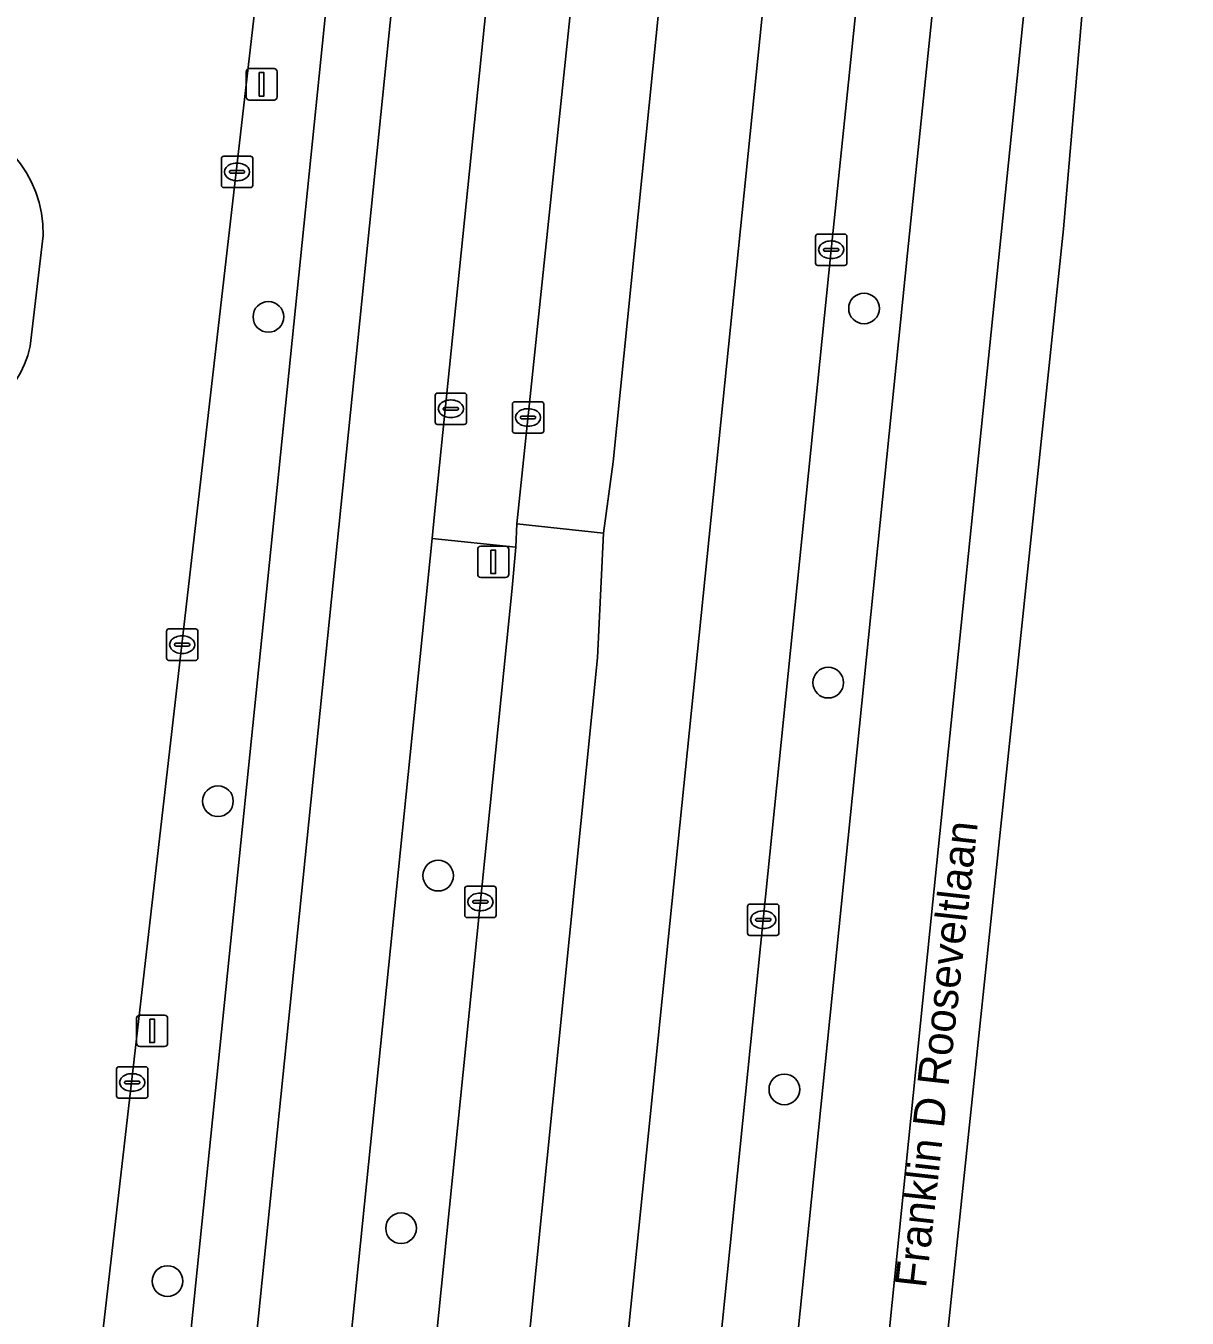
# Model space of a CAD drawing. Extents: x 160888 to 161385, y 386490 to 386908.
# Drawn here: x 161334.91 to 161371.94, y 386612.73 to 386653.93 of the extents above; entities that cross this region are included whole.
import ezdxf

# ---------------------------------------------------------------- set-up
doc = ezdxf.new("R2010")
doc.units = 0
for name, color, linetype in [('IMGEO_Berm_groen', 7, 'Continuous'), ('IMGEO_Boom', 7, 'Continuous'), ('IMGEO_Fietspad_gesloten', 7, 'Continuous'), ('IMGEO_Groenvoorziening', 7, 'Continuous'), ('IMGEO_Haag', 7, 'Continuous'), ('IMGEO_Kolk', 7, 'Continuous'), ('IMGEO_Lichtmast', 7, 'Continuous'), ('IMGEO_Openbare_ruimte_label', 7, 'Continuous'), ('IMGEO_Rijbaan_lokaal_gesloten', 7, 'Continuous'), ('IMGEO_Rijbaan_lokaal_open', 7, 'Continuous'), ('IMGEO_Voetpad_open', 7, 'Continuous')]:
    doc.layers.add(name, color=color, linetype=linetype)

msp = doc.modelspace()

# ---------------------------------------------------------------- linework, layer by layer
at = {"layer": 'IMGEO_Berm_groen'}
for points in [[(161363.024, 386646.681), (161367.022, 386685.397), (161367.598, 386691.178), (161367.683, 386693.586), (161365.398, 386693.803), (161364.593, 386685.592), (161364.125, 386681.052), (161362.491, 386665.206), (161360.59, 386646.794), (161358.423, 386625.435), (161356.553, 386606.975), (161354.948, 386591.576), (161352.778, 386570.251), (161350.673, 386549.854), (161349.854, 386541.879), (161348.259, 386526.488)], [(161350.321, 386526.461), (161352.302, 386541.627), (161357.382, 386591.194), (161359.018, 386607.209), (161363.024, 386646.681)], [(161344.884, 386581.428), (161350.408, 386635.904), (161350.537, 386637.31), (161347.861, 386637.589), (161342.161, 386581.483), (161341.141, 386571.584), (161339.032, 386551.069), (161338.136, 386542.124), (161337.443, 386534.03), (161336.548, 386526.649), (161336.452, 386525.646)]]:
    msp.add_lwpolyline(points, dxfattribs=at)
at = {"layer": 'IMGEO_Boom'}
for centre in [(161361.637, 386644.922), (161342.641, 386644.654), (161360.496, 386632.993), (161341.033, 386629.213), (161348.056, 386626.84), (161359.096, 386620.026), (161346.872, 386615.599), (161339.424, 386613.914)]:
    msp.add_circle(centre, 0.489, dxfattribs=at)
at = {"layer": 'IMGEO_Fietspad_gesloten'}
msp.add_lwpolyline([(161338.136, 386542.124), (161339.032, 386551.069), (161341.141, 386571.584), (161342.161, 386581.483), (161347.861, 386637.589), (161347.94, 386638.364), (161351.757, 386675.763), (161352.649, 386684.258), (161352.944, 386686.937), (161353.547, 386692.676), (161354.45, 386701.7), (161354.589, 386703.318), (161354.964, 386706.98), (161351.913, 386707.118), (161351.576, 386703.719), (161351.137, 386699.288), (161350.75, 386695.389), (161348.773, 386676.071), (161344.586, 386635.023), (161340.003, 386589.938), (161338.485, 386580.159)], dxfattribs=at)
at = {"layer": 'IMGEO_Groenvoorziening'}
for points in [[(161338.172, 386592.768), (161342.863, 386638.693), (161346.713, 386676.405)], [(161343.202, 386663.059), (161336.592, 386605.648), (161334.906, 386593.09), (161337.474, 386592.417)], [(161335.049, 386643.715), (161335.454, 386647.249)]]:
    msp.add_lwpolyline(points, dxfattribs=at)
for centre, radius, start, end in [((161331.73, 386647.329), 3.725, 358.7672, 84.1721), ((161331.772, 386644.452), 3.359, 267.2207, 347.325)]:
    msp.add_arc(centre, radius, start, end, dxfattribs=at)
at = {"layer": 'IMGEO_Haag'}
for points in [[(161338.172, 386592.768), (161342.863, 386638.693), (161346.713, 386676.405)], [(161343.202, 386663.059), (161336.592, 386605.648), (161334.906, 386593.09), (161337.474, 386592.417)]]:
    msp.add_lwpolyline(points, dxfattribs=at)
at = {"layer": 'IMGEO_Kolk'}
for p, q in [((161341.216, 386649.775), (161342.068, 386649.775)), ((161341.141, 386648.849), (161341.141, 386649.701)), ((161341.443, 386649.318), (161341.841, 386649.318)), ((161341.629, 386649.555), (161341.654, 386649.555)), ((161342.142, 386649.701), (161342.142, 386648.849)), ((161341.4, 386649.269), (161341.4, 386649.281)), ((161341.838, 386649.232), (161341.44, 386649.232)), ((161341.652, 386648.995), (161341.627, 386648.995)), ((161341.884, 386649.281), (161341.884, 386649.269)), ((161342.068, 386648.775), (161341.216, 386648.775)), ((161360.164, 386647.294), (161361.016, 386647.294)), ((161360.089, 386646.368), (161360.089, 386647.22)), ((161360.391, 386646.837), (161360.789, 386646.837)), ((161360.577, 386647.074), (161360.602, 386647.074)), ((161361.09, 386647.22), (161361.09, 386646.368)), ((161360.348, 386646.788), (161360.348, 386646.8)), ((161360.786, 386646.751), (161360.388, 386646.751)), ((161360.6, 386646.514), (161360.575, 386646.514)), ((161360.832, 386646.8), (161360.832, 386646.788)), ((161361.016, 386646.294), (161360.164, 386646.294)), ((161347.96, 386641.299), (161347.96, 386642.151)), ((161348.035, 386642.225), (161348.887, 386642.225)), ((161348.448, 386642.005), (161348.473, 386642.005)), ((161348.961, 386642.151), (161348.961, 386641.299)), ((161350.497, 386641.947), (161351.349, 386641.947)), ((161348.219, 386641.719), (161348.219, 386641.731)), ((161348.657, 386641.682), (161348.259, 386641.682)), ((161348.262, 386641.768), (161348.66, 386641.768)), ((161348.703, 386641.731), (161348.703, 386641.719)), ((161350.422, 386641.021), (161350.422, 386641.873)), ((161350.724, 386641.49), (161351.122, 386641.49)), ((161350.91, 386641.727), (161350.935, 386641.727)), ((161351.423, 386641.873), (161351.423, 386641.021)), ((161348.887, 386641.225), (161348.035, 386641.225)), ((161348.471, 386641.445), (161348.446, 386641.445)), ((161350.681, 386641.441), (161350.681, 386641.453)), ((161351.119, 386641.404), (161350.721, 386641.404)), ((161350.933, 386641.167), (161350.908, 386641.167)), ((161351.165, 386641.453), (161351.165, 386641.441)), ((161351.349, 386640.947), (161350.497, 386640.947)), ((161339.392, 386633.778), (161339.392, 386634.63)), ((161339.467, 386634.704), (161340.319, 386634.704)), ((161339.88, 386634.484), (161339.905, 386634.484)), ((161340.393, 386634.63), (161340.393, 386633.778)), ((161339.651, 386634.198), (161339.651, 386634.21)), ((161340.089, 386634.161), (161339.691, 386634.161)), ((161339.694, 386634.247), (161340.092, 386634.247)), ((161340.135, 386634.21), (161340.135, 386634.198)), ((161340.319, 386633.704), (161339.467, 386633.704)), ((161339.903, 386633.924), (161339.878, 386633.924)), ((161348.903, 386625.576), (161348.903, 386626.428)), ((161348.978, 386626.502), (161349.83, 386626.502)), ((161349.391, 386626.282), (161349.416, 386626.282)), ((161349.904, 386626.428), (161349.904, 386625.576)), ((161349.162, 386625.996), (161349.162, 386626.008)), ((161349.6, 386625.959), (161349.202, 386625.959)), ((161349.205, 386626.045), (161349.603, 386626.045)), ((161349.646, 386626.008), (161349.646, 386625.996)), ((161357.922, 386625.009), (161357.922, 386625.861)), ((161357.997, 386625.935), (161358.849, 386625.935)), ((161358.923, 386625.861), (161358.923, 386625.009)), ((161349.83, 386625.502), (161348.978, 386625.502)), ((161349.414, 386625.722), (161349.389, 386625.722)), ((161358.181, 386625.429), (161358.181, 386625.441)), ((161358.224, 386625.478), (161358.622, 386625.478)), ((161358.41, 386625.715), (161358.435, 386625.715)), ((161358.665, 386625.441), (161358.665, 386625.429)), ((161358.619, 386625.392), (161358.221, 386625.392)), ((161358.433, 386625.155), (161358.408, 386625.155)), ((161358.849, 386624.935), (161357.997, 386624.935)), ((161337.798, 386619.821), (161337.798, 386620.673)), ((161337.873, 386620.747), (161338.725, 386620.747)), ((161338.286, 386620.527), (161338.311, 386620.527)), ((161338.799, 386620.673), (161338.799, 386619.821)), ((161338.057, 386620.241), (161338.057, 386620.253)), ((161338.495, 386620.204), (161338.097, 386620.204)), ((161338.1, 386620.29), (161338.498, 386620.29)), ((161338.541, 386620.253), (161338.541, 386620.241)), ((161338.725, 386619.747), (161337.873, 386619.747)), ((161338.309, 386619.967), (161338.284, 386619.967))]:
    msp.add_line(p, q, dxfattribs=at)
for points in [[(161341.216, 386649.775), (161342.068, 386649.775)], [(161341.141, 386648.849), (161341.141, 386649.701)], [(161342.142, 386649.701), (161342.142, 386648.849)], [(161342.068, 386648.775), (161341.216, 386648.775)], [(161360.164, 386647.294), (161361.016, 386647.294)], [(161360.089, 386646.368), (161360.089, 386647.22)], [(161361.09, 386647.22), (161361.09, 386646.368)], [(161361.016, 386646.294), (161360.164, 386646.294)], [(161347.96, 386641.299), (161347.96, 386642.151)], [(161348.035, 386642.225), (161348.887, 386642.225)], [(161348.961, 386642.151), (161348.961, 386641.299)], [(161350.497, 386641.947), (161351.349, 386641.947)], [(161350.422, 386641.021), (161350.422, 386641.873)], [(161351.423, 386641.873), (161351.423, 386641.021)], [(161348.887, 386641.225), (161348.035, 386641.225)], [(161351.349, 386640.947), (161350.497, 386640.947)], [(161339.392, 386633.778), (161339.392, 386634.63)], [(161339.467, 386634.704), (161340.319, 386634.704)], [(161340.393, 386634.63), (161340.393, 386633.778)], [(161340.319, 386633.704), (161339.467, 386633.704)], [(161348.903, 386625.576), (161348.903, 386626.428)], [(161348.978, 386626.502), (161349.83, 386626.502)], [(161349.904, 386626.428), (161349.904, 386625.576)], [(161357.922, 386625.009), (161357.922, 386625.861)], [(161357.997, 386625.935), (161358.849, 386625.935)], [(161358.923, 386625.861), (161358.923, 386625.009)], [(161349.83, 386625.502), (161348.978, 386625.502)], [(161358.849, 386624.935), (161357.997, 386624.935)], [(161337.798, 386619.821), (161337.798, 386620.673)], [(161337.873, 386620.747), (161338.725, 386620.747)], [(161338.799, 386620.673), (161338.799, 386619.821)], [(161338.725, 386619.747), (161337.873, 386619.747)]]:
    msp.add_lwpolyline(points, dxfattribs=at)
for centre, radius, start, end in [((161341.218, 386649.699), 0.0765, 91.552, 178.448), ((161341.218, 386649.699), 0.0765, 91.552, 178.448), ((161342.066, 386649.699), 0.0765, 1.552, 88.448), ((161342.066, 386649.699), 0.0765, 1.552, 88.448), ((161341.44, 386649.278), 0.0403, 85.8775, 175.7526), ((161341.845, 386649.28), 0.0386, 1.7309, 96.639), ((161341.437, 386649.268), 0.0366, 178.938, 274.7102), ((161341.841, 386649.275), 0.043, 264.8664, 352.4533), ((161341.218, 386648.851), 0.0765, 181.552, 268.448), ((161341.218, 386648.851), 0.0765, 181.552, 268.448), ((161342.066, 386648.851), 0.0765, 271.552, 358.448), ((161342.066, 386648.851), 0.0765, 271.552, 358.448), ((161360.166, 386647.218), 0.0765, 91.552, 178.448), ((161360.166, 386647.218), 0.0765, 91.552, 178.448), ((161361.014, 386647.218), 0.0765, 1.552, 88.448), ((161361.014, 386647.218), 0.0765, 1.552, 88.448), ((161360.388, 386646.797), 0.0403, 85.8775, 175.7526), ((161360.793, 386646.799), 0.0386, 1.7309, 96.639), ((161360.385, 386646.787), 0.0366, 178.938, 274.7102), ((161360.789, 386646.794), 0.043, 264.8664, 352.4533), ((161360.166, 386646.37), 0.0765, 181.552, 268.448), ((161360.166, 386646.37), 0.0765, 181.552, 268.448), ((161361.014, 386646.37), 0.0765, 271.552, 358.448), ((161361.014, 386646.37), 0.0765, 271.552, 358.448), ((161348.037, 386642.149), 0.0765, 91.552, 178.448), ((161348.037, 386642.149), 0.0765, 91.552, 178.448), ((161348.885, 386642.149), 0.0765, 1.552, 88.448), ((161348.885, 386642.149), 0.0765, 1.552, 88.448), ((161350.499, 386641.871), 0.0765, 91.552, 178.448), ((161350.499, 386641.871), 0.0765, 91.552, 178.448), ((161351.347, 386641.871), 0.0765, 1.552, 88.448), ((161351.347, 386641.871), 0.0765, 1.552, 88.448), ((161348.259, 386641.728), 0.0403, 85.8775, 175.7526), ((161348.256, 386641.718), 0.0366, 178.938, 274.7102), ((161348.66, 386641.725), 0.043, 264.8664, 352.4533), ((161348.664, 386641.73), 0.0386, 1.7309, 96.639), ((161350.721, 386641.45), 0.0403, 85.8775, 175.7526), ((161351.126, 386641.452), 0.0386, 1.7309, 96.639), ((161348.037, 386641.301), 0.0765, 181.552, 268.448), ((161348.037, 386641.301), 0.0765, 181.552, 268.448), ((161348.885, 386641.301), 0.0765, 271.552, 358.448), ((161348.885, 386641.301), 0.0765, 271.552, 358.448), ((161350.718, 386641.44), 0.0366, 178.938, 274.7102), ((161351.122, 386641.447), 0.043, 264.8664, 352.4533), ((161350.499, 386641.023), 0.0765, 181.552, 268.448), ((161350.499, 386641.023), 0.0765, 181.552, 268.448), ((161351.347, 386641.023), 0.0765, 271.552, 358.448), ((161351.347, 386641.023), 0.0765, 271.552, 358.448), ((161339.469, 386634.628), 0.0765, 91.552, 178.448), ((161339.469, 386634.628), 0.0765, 91.552, 178.448), ((161340.317, 386634.628), 0.0765, 1.552, 88.448), ((161340.317, 386634.628), 0.0765, 1.552, 88.448), ((161339.691, 386634.207), 0.0403, 85.8775, 175.7526), ((161339.688, 386634.197), 0.0366, 178.938, 274.7102), ((161340.092, 386634.204), 0.043, 264.8664, 352.4533), ((161340.096, 386634.209), 0.0386, 1.7309, 96.639), ((161339.469, 386633.78), 0.0765, 181.552, 268.448), ((161339.469, 386633.78), 0.0765, 181.552, 268.448), ((161340.317, 386633.78), 0.0765, 271.552, 358.448), ((161340.317, 386633.78), 0.0765, 271.552, 358.448), ((161348.98, 386626.426), 0.0765, 91.552, 178.448), ((161348.98, 386626.426), 0.0765, 91.552, 178.448), ((161349.828, 386626.426), 0.0765, 1.552, 88.448), ((161349.828, 386626.426), 0.0765, 1.552, 88.448), ((161349.202, 386626.005), 0.0403, 85.8775, 175.7526), ((161349.199, 386625.995), 0.0366, 178.938, 274.7102), ((161349.603, 386626.002), 0.043, 264.8664, 352.4533), ((161349.607, 386626.007), 0.0386, 1.7309, 96.639), ((161357.999, 386625.859), 0.0765, 91.552, 178.448), ((161357.999, 386625.859), 0.0765, 91.552, 178.448), ((161358.847, 386625.859), 0.0765, 1.552, 88.448), ((161358.847, 386625.859), 0.0765, 1.552, 88.448), ((161348.98, 386625.578), 0.0765, 181.552, 268.448), ((161348.98, 386625.578), 0.0765, 181.552, 268.448), ((161349.828, 386625.578), 0.0765, 271.552, 358.448), ((161349.828, 386625.578), 0.0765, 271.552, 358.448), ((161358.221, 386625.438), 0.0403, 85.8775, 175.7526), ((161358.218, 386625.428), 0.0366, 178.938, 274.7102), ((161358.622, 386625.435), 0.043, 264.8664, 352.4533), ((161358.626, 386625.44), 0.0386, 1.7309, 96.639), ((161357.999, 386625.011), 0.0765, 181.552, 268.448), ((161357.999, 386625.011), 0.0765, 181.552, 268.448), ((161358.847, 386625.011), 0.0765, 271.552, 358.448), ((161358.847, 386625.011), 0.0765, 271.552, 358.448), ((161337.875, 386620.671), 0.0765, 91.552, 178.448), ((161337.875, 386620.671), 0.0765, 91.552, 178.448), ((161338.723, 386620.671), 0.0765, 1.552, 88.448), ((161338.723, 386620.671), 0.0765, 1.552, 88.448), ((161338.097, 386620.25), 0.0403, 85.8775, 175.7526), ((161338.094, 386620.24), 0.0366, 178.938, 274.7102), ((161338.498, 386620.247), 0.043, 264.8664, 352.4533), ((161338.502, 386620.252), 0.0386, 1.7309, 96.639), ((161337.875, 386619.823), 0.0765, 181.552, 268.448), ((161337.875, 386619.823), 0.0765, 181.552, 268.448), ((161338.723, 386619.823), 0.0765, 271.552, 358.448), ((161338.723, 386619.823), 0.0765, 271.552, 358.448)]:
    msp.add_arc(centre, radius, start, end, dxfattribs=at)
for centre, major_axis, ratio, start_param, end_param in [((161341.628, 386649.275), (-0.387, 0.002), 0.722429, 4.712389, 7.853982), ((161341.653, 386649.275), (-0.39, 0.002), 0.717154, 1.570796, 4.712389), ((161360.576, 386646.794), (-0.387, 0.002), 0.722429, 4.712389, 7.853982), ((161360.601, 386646.794), (-0.39, 0.002), 0.717154, 1.570796, 4.712389), ((161348.447, 386641.725), (-0.387, 0.002), 0.722429, 4.712389, 7.853982), ((161348.472, 386641.725), (-0.39, 0.002), 0.717154, 1.570796, 4.712389), ((161350.909, 386641.447), (-0.387, 0.002), 0.722429, 4.712389, 7.853982), ((161350.934, 386641.447), (-0.39, 0.002), 0.717154, 1.570796, 4.712389), ((161339.879, 386634.204), (-0.387, 0.002), 0.722429, 4.712389, 7.853982), ((161339.904, 386634.204), (-0.39, 0.002), 0.717154, 1.570796, 4.712389), ((161349.39, 386626.002), (-0.387, 0.002), 0.722429, 4.712389, 7.853982), ((161349.415, 386626.002), (-0.39, 0.002), 0.717154, 1.570796, 4.712389), ((161358.409, 386625.435), (-0.387, 0.002), 0.722429, 4.712389, 7.853982), ((161358.434, 386625.435), (-0.39, 0.002), 0.717154, 1.570796, 4.712389), ((161338.285, 386620.247), (-0.387, 0.002), 0.722429, 4.712389, 7.853982), ((161338.31, 386620.247), (-0.39, 0.002), 0.717154, 1.570796, 4.712389)]:
    msp.add_ellipse(centre, major_axis=major_axis, ratio=ratio, start_param=start_param, end_param=end_param, dxfattribs=at)
at = {"layer": 'IMGEO_Lichtmast'}
for p, q in [((161341.931, 386651.667), (161341.931, 386652.467)), ((161341.931, 386652.467), (161341.931, 386651.667)), ((161342.031, 386652.567), (161342.821, 386652.567)), ((161342.821, 386652.567), (161342.031, 386652.567)), ((161342.921, 386652.467), (161342.921, 386651.667)), ((161342.921, 386651.667), (161342.921, 386652.467)), ((161342.821, 386651.567), (161342.031, 386651.567)), ((161342.031, 386651.567), (161342.821, 386651.567)), ((161349.318, 386636.445), (161349.318, 386637.245)), ((161349.318, 386637.245), (161349.318, 386636.445)), ((161349.418, 386637.345), (161350.208, 386637.345)), ((161350.208, 386637.345), (161349.418, 386637.345)), ((161350.308, 386637.245), (161350.308, 386636.445)), ((161350.308, 386636.445), (161350.308, 386637.245)), ((161350.208, 386636.345), (161349.418, 386636.345)), ((161349.418, 386636.345), (161350.208, 386636.345)), ((161338.438, 386621.492), (161338.438, 386622.292)), ((161338.438, 386622.292), (161338.438, 386621.492)), ((161338.538, 386622.392), (161339.328, 386622.392)), ((161339.328, 386622.392), (161338.538, 386622.392)), ((161339.428, 386622.292), (161339.428, 386621.492)), ((161339.428, 386621.492), (161339.428, 386622.292)), ((161339.328, 386621.392), (161338.538, 386621.392)), ((161338.538, 386621.392), (161339.328, 386621.392))]:
    msp.add_line(p, q, dxfattribs=at)
for points in [[(161342.351, 386652.442), (161342.501, 386652.442), (161342.501, 386651.692), (161342.351, 386651.692), (161342.351, 386652.442)], [(161349.738, 386637.22), (161349.888, 386637.22), (161349.888, 386636.47), (161349.738, 386636.47), (161349.738, 386637.22)], [(161338.858, 386622.267), (161339.008, 386622.267), (161339.008, 386621.517), (161338.858, 386621.517), (161338.858, 386622.267)]]:
    msp.add_lwpolyline(points, dxfattribs=at)
for centre, start, end in [((161342.031, 386652.467), 90, 180), ((161342.031, 386652.467), 90, 180), ((161342.821, 386652.467), 0, 90), ((161342.821, 386652.467), 360, 90), ((161342.031, 386651.667), 180, 270), ((161342.031, 386651.667), 180, 270), ((161342.821, 386651.667), 270, 0), ((161342.821, 386651.667), 270, 0), ((161349.418, 386637.245), 90, 180), ((161349.418, 386637.245), 90, 180), ((161350.208, 386637.245), 0, 90), ((161350.208, 386637.245), 360, 90), ((161349.418, 386636.445), 180, 270), ((161349.418, 386636.445), 180, 270), ((161350.208, 386636.445), 270, 0), ((161350.208, 386636.445), 270, 0), ((161338.538, 386622.292), 90, 180), ((161338.538, 386622.292), 90, 180), ((161339.328, 386622.292), 0, 90), ((161339.328, 386622.292), 360, 90), ((161338.538, 386621.492), 180, 270), ((161338.538, 386621.492), 180, 270), ((161339.328, 386621.492), 270, 0), ((161339.328, 386621.492), 270, 0)]:
    msp.add_arc(centre, 0.1, start, end, dxfattribs=at)
at = {"layer": 'IMGEO_Rijbaan_lokaal_gesloten'}
for points in [[(161370.722, 386693.301), (161367.683, 386693.586), (161367.598, 386691.178), (161367.022, 386685.397), (161363.024, 386646.681), (161359.018, 386607.209), (161357.382, 386591.194), (161352.302, 386541.627), (161350.321, 386526.461), (161350.319, 386526.26), (161349.828, 386522.538), (161353.345, 386522.715), (161363.732, 386625.065), (161368.799, 386674.486)], [(161355.54, 386522.826), (161356.711, 386535.543), (161359.985, 386571.09), (161367.997, 386647.461), (161371.943, 386693.186), (161370.722, 386693.301), (161368.799, 386674.486), (161363.732, 386625.065), (161353.345, 386522.715)], [(161361.036, 386681.278), (161357.895, 386681.509), (161357.486, 386677.479), (161357.474, 386677.379), (161357.293, 386676.298), (161357.015, 386675.238), (161357.193, 386675.204), (161353.638, 386640.03), (161353.333, 386637.758), (161353.14, 386633.788), (161350.996, 386612.554), (161343.29, 386537.458), (161341.732, 386522.048), (161344.957, 386522.245), (161345.695, 386529.16), (161349.223, 386564.812), (161353.824, 386609.435), (161360.75, 386677.447)], [(161349.854, 386541.879), (161350.673, 386549.854), (161352.778, 386570.251), (161354.948, 386591.576), (161356.553, 386606.975), (161358.423, 386625.435), (161360.59, 386646.794), (161362.491, 386665.206), (161364.125, 386681.052), (161361.036, 386681.278), (161360.75, 386677.447), (161353.824, 386609.435), (161349.223, 386564.812), (161345.695, 386529.16), (161344.957, 386522.245), (161347.834, 386522.421), (161348.225, 386526.261), (161348.259, 386526.488)], [(161353.211, 386660.371), (161352.745, 386658.865), (161350.569, 386638.061), (161353.333, 386637.758), (161353.638, 386640.03), (161357.193, 386675.204), (161357.015, 386675.238), (161354.412, 386665.035)], [(161353.333, 386637.758), (161350.569, 386638.061), (161350.537, 386637.31), (161350.408, 386635.904), (161344.884, 386581.428), (161343.814, 386571.25), (161341.755, 386550.887), (161339.538, 386529.553), (161339.176, 386526.026), (161339.147, 386525.679), (161338.762, 386521.866), (161341.732, 386522.048), (161343.29, 386537.458), (161350.996, 386612.554), (161353.14, 386633.788)]]:
    msp.add_lwpolyline(points, close=True, dxfattribs=at)
at = {"layer": 'IMGEO_Rijbaan_lokaal_open'}
msp.add_lwpolyline([(161347.861, 386637.589), (161350.537, 386637.31), (161350.569, 386638.061), (161352.745, 386658.865), (161353.211, 386660.371), (161354.412, 386665.035), (161357.015, 386675.238), (161351.757, 386675.763), (161347.94, 386638.364)], close=True, dxfattribs=at)
for points in [[(161334.906, 386593.09), (161336.592, 386605.648), (161343.202, 386663.059)], [(161335.454, 386647.249), (161335.049, 386643.715)]]:
    msp.add_lwpolyline(points, dxfattribs=at)
for centre, radius, start, end in [((161331.73, 386647.329), 3.725, 358.7672, 84.1721), ((161331.772, 386644.452), 3.359, 267.2207, 347.325)]:
    msp.add_arc(centre, radius, start, end, dxfattribs=at)
at = {"layer": 'IMGEO_Voetpad_open'}
for points in [[(161340.003, 386589.938), (161344.586, 386635.023), (161348.773, 386676.071), (161350.75, 386695.389)], [(161348.346, 386692.534), (161346.713, 386676.405), (161342.863, 386638.693), (161338.172, 386592.768)]]:
    msp.add_lwpolyline(points, dxfattribs=at)

# ---------------------------------------------------------------- texts
at = {"layer": 'IMGEO_Openbare_ruimte_label'}
msp.add_text('Franklin D Rooseveltlaan', height=1, rotation=83.6282, dxfattribs=at).set_placement((161363.611, 386613.672))

doc.saveas('drawing.dxf')
